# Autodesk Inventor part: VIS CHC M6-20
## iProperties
Created: 2004-11
Part Number: VIS CHC M6-20
Document SubType Name: Modeling
Designer: Bruno
Manufacturer: Standard
Standards Organization: Custom
Author: Bruno
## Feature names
1. Base1
